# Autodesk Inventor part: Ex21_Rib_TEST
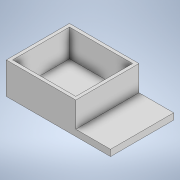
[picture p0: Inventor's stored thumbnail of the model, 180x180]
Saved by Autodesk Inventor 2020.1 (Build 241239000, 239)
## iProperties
Created: 2019-11
Part Number: Ex21_Rib_TEST
Material: Generic
Document SubType Name: Modeling
Designer: Synergysoft Dell02
Density: 1 g/cm^3
Appearance: Default
Author: Synergysoft Dell02
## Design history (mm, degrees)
sketch "Sketch1"
  geometry: L1 (0, 0)-(0, 50); L2 (0, 50)-(10, 50); L3 (10, 50)-(10, 10); L4 (10, 10)-(65, 10); L5 (65, 10)-(65, 0); L6 (65, 0)-(0, 0)
  constraints: 12 end point, 4 perpendicular, 1 parallel, 1 vertical
  dimensions: "d0" = 50 distance of L1.start L1.end; "d4" = 10 distance of L1.end L2.end; "d5" = 10 distance of L4.end L5.end; "d6" = 65 distance of L5.end L1.start
extrude "Extrusion1" new body sketch "Sketch1" distance "d7" = 100; taper "d8" = 0 deg
sketch "Sketch2"
  geometry: L1 (0, 50)-(0, 0) reference; L2 (0, 0)-(100, 0) reference; L3 (100, 50)-(100, 0) reference; L4 (0, 50)-(100, 50) reference; 1 further point
extrude "Extrusion2" join sketch "Sketch2" distance "d9" = 100; taper "d10" = 0 deg
sketch "Sketch3"
  geometry: L1 (0, 100)-(-110, 100) reference; L2 (-110, 0)-(-110, 100) reference; L3 (0, 0)-(-110, 0) reference; L4 (0, 100)-(0, 0) reference; L5 (-105, 95)-(-5, 95); L6 (-5, 95)-(-5, 5); L7 (-5, 5)-(-105, 5); L8 (-105, 5)-(-105, 95); 1 further point
  constraints: 8 end point, 3 other
  dimensions: "d11" = 5 distance between parallel lines of L2 L8
extrude "Extrusion3" cut sketch "Sketch3" stored distance "d12" = 10; taper "d13" = -5 deg
body "Solid1"
node "Projected Loop1"
node "Projected Loop2"
